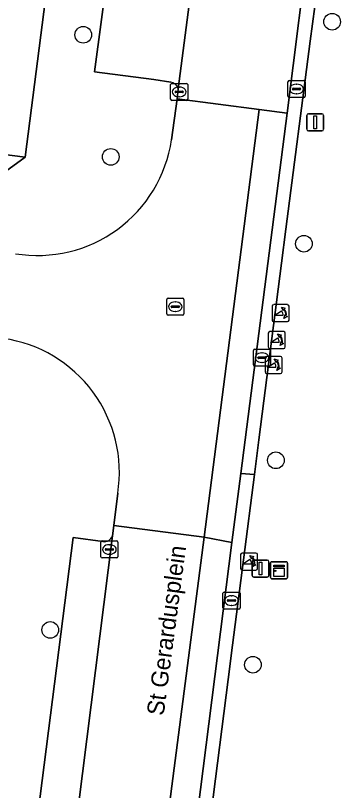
# Model space of a CAD drawing. Extents: x 161692 to 162379, y 380760 to 381678.
# Drawn here: x 162016.68 to 162035.73, y 381271.3 to 381316.74 of the extents above; entities that cross this region are included whole.
import ezdxf

# ---------------------------------------------------------------- set-up
doc = ezdxf.new("R2010")
doc.units = 0
for name, color, linetype in [('IMGEO_Boom', 7, 'Continuous'), ('IMGEO_Erf', 7, 'Continuous'), ('IMGEO_Kast', 7, 'Continuous'), ('IMGEO_Kolk', 7, 'Continuous'), ('IMGEO_Lichtmast', 7, 'Continuous'), ('IMGEO_Openbare_ruimte_label', 7, 'Continuous'), ('IMGEO_Parkeervlak_open', 7, 'Continuous'), ('IMGEO_Poller', 7, 'Continuous'), ('IMGEO_Rijbaan_lokaal_open', 7, 'Continuous'), ('IMGEO_Rioolput', 7, 'Continuous'), ('IMGEO_Voetpad_open', 7, 'Continuous')]:
    doc.layers.add(name, color=color, linetype=linetype)

msp = doc.modelspace()

# ---------------------------------------------------------------- linework, layer by layer
at = {"layer": 'IMGEO_Boom'}
for centre in [(162035.245, 381316.377), (162020.654, 381315.61), (162022.263, 381308.45), (162033.59, 381303.36), (162031.947, 381290.657), (162018.718, 381280.711), (162030.602, 381278.673)]:
    msp.add_circle(centre, 0.489, dxfattribs=at)
at = {"layer": 'IMGEO_Erf'}
msp.add_lwpolyline([(161995.661, 381319.221), (161995.164, 381315.349), (161989.105, 381316.129), (161988.599, 381312.051), (161994.487, 381311.32), (161997.312, 381310.962), (162007.146, 381309.715), (162017.252, 381308.434), (162021.166, 381339.052)], dxfattribs=at)
at = {"layer": 'IMGEO_Kast'}
for p, q in [((162031.634, 381283.786), (162031.634, 381284.627)), ((162031.634, 381284.627), (162031.634, 381283.786)), ((162031.709, 381284.711), (162032.55, 381284.711)), ((162032.55, 381284.711), (162031.709, 381284.711)), ((162032.634, 381284.636), (162032.634, 381283.795)), ((162032.634, 381283.795), (162032.634, 381284.636)), ((162032.559, 381283.711), (162031.718, 381283.711)), ((162031.718, 381283.711), (162032.559, 381283.711))]:
    msp.add_line(p, q, dxfattribs=at)
for points in [[(162031.829, 381284.501), (162032.429, 381284.501), (162032.429, 381284.416), (162031.829, 381284.416), (162031.829, 381284.501)], [(162031.829, 381284.326), (162032.429, 381284.326), (162032.429, 381283.837), (162031.829, 381283.837), (162031.829, 381284.326)]]:
    msp.add_lwpolyline(points, dxfattribs=at)
msp.add_circle((162031.913, 381284.175), 0.0377, dxfattribs=at)
for centre, start, end in [((162031.712, 381284.633), 92.4484, 184.2845), ((162031.712, 381284.633), 92.4484, 184.2845), ((162032.556, 381284.633), 2.4484, 94.2845), ((162032.556, 381284.633), 2.4484, 94.2845), ((162031.712, 381283.789), 182.4484, 274.2845), ((162031.712, 381283.789), 182.4484, 274.2845), ((162032.556, 381283.789), 272.4484, 4.2845), ((162032.556, 381283.789), 272.4484, 4.2845)]:
    msp.add_arc(centre, 0.0779, start, end, dxfattribs=at)
at = {"layer": 'IMGEO_Kolk'}
for p, q in [((162025.775, 381311.834), (162025.775, 381312.686)), ((162025.85, 381312.76), (162026.702, 381312.76)), ((162026.776, 381312.686), (162026.776, 381311.834)), ((162032.656, 381312.005), (162032.656, 381312.857)), ((162032.731, 381312.931), (162033.583, 381312.931)), ((162033.144, 381312.711), (162033.169, 381312.711)), ((162033.657, 381312.857), (162033.657, 381312.005)), ((162026.034, 381312.254), (162026.034, 381312.266)), ((162026.472, 381312.217), (162026.074, 381312.217)), ((162026.077, 381312.303), (162026.475, 381312.303)), ((162026.263, 381312.54), (162026.288, 381312.54)), ((162026.518, 381312.266), (162026.518, 381312.254)), ((162032.915, 381312.425), (162032.915, 381312.437)), ((162033.353, 381312.388), (162032.955, 381312.388)), ((162032.958, 381312.474), (162033.356, 381312.474)), ((162033.399, 381312.437), (162033.399, 381312.425)), ((162026.702, 381311.76), (162025.85, 381311.76)), ((162026.286, 381311.98), (162026.261, 381311.98)), ((162033.583, 381311.931), (162032.731, 381311.931)), ((162033.167, 381312.151), (162033.142, 381312.151)), ((162030.632, 381296.25), (162030.632, 381297.102)), ((162030.707, 381297.176), (162031.559, 381297.176)), ((162031.12, 381296.956), (162031.145, 381296.956)), ((162031.633, 381297.102), (162031.633, 381296.25)), ((162030.891, 381296.67), (162030.891, 381296.682)), ((162031.329, 381296.633), (162030.931, 381296.633)), ((162030.934, 381296.719), (162031.332, 381296.719)), ((162031.143, 381296.396), (162031.118, 381296.396)), ((162031.375, 381296.682), (162031.375, 381296.67)), ((162031.559, 381296.176), (162030.707, 381296.176)), ((162021.687, 381285.004), (162021.687, 381285.856)), ((162021.762, 381285.93), (162022.614, 381285.93)), ((162022.688, 381285.856), (162022.688, 381285.004)), ((162021.946, 381285.424), (162021.946, 381285.436)), ((162021.989, 381285.473), (162022.387, 381285.473)), ((162022.175, 381285.71), (162022.2, 381285.71)), ((162022.43, 381285.436), (162022.43, 381285.424)), ((162022.384, 381285.387), (162021.986, 381285.387)), ((162022.198, 381285.15), (162022.173, 381285.15)), ((162022.614, 381284.93), (162021.762, 381284.93)), ((162028.845, 381282.007), (162028.845, 381282.859)), ((162028.92, 381282.933), (162029.772, 381282.933)), ((162029.333, 381282.713), (162029.358, 381282.713)), ((162029.846, 381282.859), (162029.846, 381282.007)), ((162029.104, 381282.427), (162029.104, 381282.439)), ((162029.542, 381282.39), (162029.144, 381282.39)), ((162029.147, 381282.476), (162029.545, 381282.476)), ((162029.588, 381282.439), (162029.588, 381282.427)), ((162029.772, 381281.933), (162028.92, 381281.933)), ((162029.356, 381282.153), (162029.331, 381282.153))]:
    msp.add_line(p, q, dxfattribs=at)
for points in [[(162025.775, 381311.834), (162025.775, 381312.686)], [(162025.85, 381312.76), (162026.702, 381312.76)], [(162026.776, 381312.686), (162026.776, 381311.834)], [(162032.656, 381312.005), (162032.656, 381312.857)], [(162032.731, 381312.931), (162033.583, 381312.931)], [(162033.657, 381312.857), (162033.657, 381312.005)], [(162026.702, 381311.76), (162025.85, 381311.76)], [(162033.583, 381311.931), (162032.731, 381311.931)], [(162030.632, 381296.25), (162030.632, 381297.102)], [(162030.707, 381297.176), (162031.559, 381297.176)], [(162031.633, 381297.102), (162031.633, 381296.25)], [(162031.559, 381296.176), (162030.707, 381296.176)], [(162021.687, 381285.004), (162021.687, 381285.856)], [(162021.762, 381285.93), (162022.614, 381285.93)], [(162022.688, 381285.856), (162022.688, 381285.004)], [(162022.614, 381284.93), (162021.762, 381284.93)], [(162028.845, 381282.007), (162028.845, 381282.859)], [(162028.92, 381282.933), (162029.772, 381282.933)], [(162029.846, 381282.859), (162029.846, 381282.007)], [(162029.772, 381281.933), (162028.92, 381281.933)]]:
    msp.add_lwpolyline(points, dxfattribs=at)
for centre, radius, start, end in [((162025.852, 381312.684), 0.0765, 91.552, 178.448), ((162025.852, 381312.684), 0.0765, 91.552, 178.448), ((162026.7, 381312.684), 0.0765, 1.552, 88.448), ((162026.7, 381312.684), 0.0765, 1.552, 88.448), ((162032.733, 381312.855), 0.0765, 91.552, 178.448), ((162032.733, 381312.855), 0.0765, 91.552, 178.448), ((162033.581, 381312.855), 0.0765, 1.552, 88.448), ((162033.581, 381312.855), 0.0765, 1.552, 88.448), ((162026.074, 381312.263), 0.0403, 85.8775, 175.7526), ((162026.071, 381312.253), 0.0366, 178.938, 274.7102), ((162026.475, 381312.26), 0.043, 264.8664, 352.4533), ((162026.479, 381312.265), 0.0386, 1.7309, 96.639), ((162032.955, 381312.434), 0.0403, 85.8775, 175.7526), ((162032.952, 381312.424), 0.0366, 178.938, 274.7102), ((162033.356, 381312.431), 0.043, 264.8664, 352.4533), ((162033.36, 381312.436), 0.0386, 1.7309, 96.639), ((162025.852, 381311.836), 0.0765, 181.552, 268.448), ((162025.852, 381311.836), 0.0765, 181.552, 268.448), ((162026.7, 381311.836), 0.0765, 271.552, 358.448), ((162026.7, 381311.836), 0.0765, 271.552, 358.448), ((162032.733, 381312.007), 0.0765, 181.552, 268.448), ((162032.733, 381312.007), 0.0765, 181.552, 268.448), ((162033.581, 381312.007), 0.0765, 271.552, 358.448), ((162033.581, 381312.007), 0.0765, 271.552, 358.448), ((162030.709, 381297.1), 0.0765, 91.552, 178.448), ((162030.709, 381297.1), 0.0765, 91.552, 178.448), ((162031.557, 381297.1), 0.0765, 1.552, 88.448), ((162031.557, 381297.1), 0.0765, 1.552, 88.448), ((162030.931, 381296.679), 0.0403, 85.8775, 175.7526), ((162030.928, 381296.669), 0.0366, 178.938, 274.7102), ((162031.332, 381296.676), 0.043, 264.8664, 352.4533), ((162031.336, 381296.681), 0.0386, 1.7309, 96.639), ((162030.709, 381296.252), 0.0765, 181.552, 268.448), ((162030.709, 381296.252), 0.0765, 181.552, 268.448), ((162031.557, 381296.252), 0.0765, 271.552, 358.448), ((162031.557, 381296.252), 0.0765, 271.552, 358.448), ((162021.764, 381285.854), 0.0765, 91.552, 178.448), ((162021.764, 381285.854), 0.0765, 91.552, 178.448), ((162022.612, 381285.854), 0.0765, 1.552, 88.448), ((162022.612, 381285.854), 0.0765, 1.552, 88.448), ((162021.986, 381285.433), 0.0403, 85.8775, 175.7526), ((162021.983, 381285.423), 0.0366, 178.938, 274.7102), ((162022.387, 381285.43), 0.043, 264.8664, 352.4533), ((162022.391, 381285.435), 0.0386, 1.7309, 96.639), ((162021.764, 381285.006), 0.0765, 181.552, 268.448), ((162021.764, 381285.006), 0.0765, 181.552, 268.448), ((162022.612, 381285.006), 0.0765, 271.552, 358.448), ((162022.612, 381285.006), 0.0765, 271.552, 358.448), ((162028.922, 381282.857), 0.0765, 91.552, 178.448), ((162028.922, 381282.857), 0.0765, 91.552, 178.448), ((162029.77, 381282.857), 0.0765, 1.552, 88.448), ((162029.77, 381282.857), 0.0765, 1.552, 88.448), ((162029.144, 381282.436), 0.0403, 85.8775, 175.7526), ((162029.141, 381282.426), 0.0366, 178.938, 274.7102), ((162029.545, 381282.433), 0.043, 264.8664, 352.4533), ((162029.549, 381282.438), 0.0386, 1.7309, 96.639), ((162028.922, 381282.009), 0.0765, 181.552, 268.448), ((162028.922, 381282.009), 0.0765, 181.552, 268.448), ((162029.77, 381282.009), 0.0765, 271.552, 358.448), ((162029.77, 381282.009), 0.0765, 271.552, 358.448)]:
    msp.add_arc(centre, radius, start, end, dxfattribs=at)
for centre, major_axis, ratio, start_param, end_param in [((162033.143, 381312.431), (-0.387, 0.002), 0.722429, 4.712389, 7.853982), ((162033.168, 381312.431), (-0.39, 0.002), 0.717154, 1.570796, 4.712389), ((162026.262, 381312.26), (-0.387, 0.002), 0.722429, 4.712389, 7.853982), ((162026.287, 381312.26), (-0.39, 0.002), 0.717154, 1.570796, 4.712389), ((162031.119, 381296.676), (-0.387, 0.002), 0.722429, 4.712389, 7.853982), ((162031.144, 381296.676), (-0.39, 0.002), 0.717154, 1.570796, 4.712389), ((162022.174, 381285.43), (-0.387, 0.002), 0.722429, 4.712389, 7.853982), ((162022.199, 381285.43), (-0.39, 0.002), 0.717154, 1.570796, 4.712389), ((162029.332, 381282.433), (-0.387, 0.002), 0.722429, 4.712389, 7.853982), ((162029.357, 381282.433), (-0.39, 0.002), 0.717154, 1.570796, 4.712389)]:
    msp.add_ellipse(centre, major_axis=major_axis, ratio=ratio, start_param=start_param, end_param=end_param, dxfattribs=at)
at = {"layer": 'IMGEO_Lichtmast'}
for p, q in [((162033.752, 381310.078), (162033.752, 381310.878)), ((162033.752, 381310.878), (162033.752, 381310.078)), ((162033.852, 381310.978), (162034.642, 381310.978)), ((162034.642, 381310.978), (162033.852, 381310.978)), ((162034.742, 381310.878), (162034.742, 381310.078)), ((162034.742, 381310.078), (162034.742, 381310.878)), ((162034.642, 381309.978), (162033.852, 381309.978)), ((162033.852, 381309.978), (162034.642, 381309.978)), ((162030.552, 381283.911), (162030.552, 381284.711)), ((162030.552, 381284.711), (162030.552, 381283.911)), ((162030.652, 381284.811), (162031.442, 381284.811)), ((162031.442, 381284.811), (162030.652, 381284.811)), ((162031.542, 381284.711), (162031.542, 381283.911)), ((162031.542, 381283.911), (162031.542, 381284.711)), ((162031.442, 381283.811), (162030.652, 381283.811)), ((162030.652, 381283.811), (162031.442, 381283.811))]:
    msp.add_line(p, q, dxfattribs=at)
for points in [[(162034.172, 381310.853), (162034.322, 381310.853), (162034.322, 381310.103), (162034.172, 381310.103), (162034.172, 381310.853)], [(162030.972, 381284.686), (162031.122, 381284.686), (162031.122, 381283.936), (162030.972, 381283.936), (162030.972, 381284.686)]]:
    msp.add_lwpolyline(points, dxfattribs=at)
for centre, start, end in [((162033.852, 381310.878), 90, 180), ((162033.852, 381310.878), 90, 180), ((162034.642, 381310.878), 0, 90), ((162034.642, 381310.878), 360, 90), ((162033.852, 381310.078), 180, 270), ((162033.852, 381310.078), 180, 270), ((162034.642, 381310.078), 270, 0), ((162034.642, 381310.078), 270, 0), ((162030.652, 381284.711), 90, 180), ((162030.652, 381284.711), 90, 180), ((162031.442, 381284.711), 0, 90), ((162031.442, 381284.711), 360, 90), ((162030.652, 381283.911), 180, 270), ((162030.652, 381283.911), 180, 270), ((162031.442, 381283.911), 270, 0), ((162031.442, 381283.911), 270, 0)]:
    msp.add_arc(centre, 0.1, start, end, dxfattribs=at)
at = {"layer": 'IMGEO_Parkeervlak_open'}
for points in [[(162028.406, 381332.608), (162026.443, 381332.823), (162024.266, 381333.061), (162023.951, 381333.096), (162022.62, 381323.253), (162021.322, 381313.439), (162024.793, 381312.979), (162025.78, 381312.831)], [(162026.227, 381312.442), (162027.445, 381321.903), (162028.924, 381332.977)], [(162035.502, 381327.199), (162035.478, 381327.014), (162035.224, 381325.046), (162034.22, 381317.265), (162033.958, 381315.236), (162032.535, 381304.211), (162032.276, 381302.209), (162030.94, 381291.863), (162030.685, 381289.819), (162029.406, 381279.816), (162029.149, 381277.807), (162028.148, 381269.978), (162027.886, 381267.928), (162027.77, 381267.028)], [(162021.803, 381285.896), (162020.053, 381286.125), (162017.647, 381267.141), (162019.426, 381266.906)], [(162019.864, 381266.409), (162022.365, 381286.225)]]:
    msp.add_lwpolyline(points, dxfattribs=at)
for centre, radius, start, end in [((162025.73, 381312.322), 0.511, 13.5264, 84.411), ((162021.895, 381286.384), 0.497, 259.3692, 341.321)]:
    msp.add_arc(centre, radius, start, end, dxfattribs=at)
at = {"layer": 'IMGEO_Poller'}
for p, q in [((162031.726, 381299.69), (162031.726, 381298.883)), ((162031.726, 381299.69), (162031.726, 381298.883)), ((162032.628, 381299.785), (162031.82, 381299.785)), ((162032.628, 381299.785), (162031.82, 381299.785)), ((162032.722, 381298.883), (162032.722, 381299.69)), ((162032.722, 381298.883), (162032.722, 381299.69)), ((162031.82, 381298.788), (162032.628, 381298.788)), ((162031.82, 381298.788), (162032.628, 381298.788)), ((162032.404, 381298.206), (162031.596, 381298.206)), ((162032.404, 381298.206), (162031.596, 381298.206)), ((162031.502, 381298.111), (162031.502, 381297.304)), ((162031.502, 381298.111), (162031.502, 381297.304)), ((162032.498, 381297.304), (162032.498, 381298.111)), ((162032.498, 381297.304), (162032.498, 381298.111)), ((162031.596, 381297.209), (162032.404, 381297.209)), ((162031.596, 381297.209), (162032.404, 381297.209)), ((162031.311, 381296.649), (162031.311, 381295.842)), ((162031.311, 381296.649), (162031.311, 381295.842)), ((162032.213, 381296.744), (162031.405, 381296.744)), ((162032.213, 381296.744), (162031.405, 381296.744)), ((162032.307, 381295.842), (162032.307, 381296.649)), ((162032.307, 381295.842), (162032.307, 381296.649)), ((162031.405, 381295.747), (162032.213, 381295.747)), ((162031.405, 381295.747), (162032.213, 381295.747)), ((162029.875, 381285.126), (162029.875, 381284.319)), ((162029.875, 381285.126), (162029.875, 381284.319)), ((162030.777, 381285.221), (162029.969, 381285.221)), ((162030.777, 381285.221), (162029.969, 381285.221)), ((162030.871, 381284.319), (162030.871, 381285.126)), ((162030.871, 381284.319), (162030.871, 381285.126)), ((162029.969, 381284.224), (162030.777, 381284.224)), ((162029.969, 381284.224), (162030.777, 381284.224))]:
    msp.add_line(p, q, dxfattribs=at)
for points in [[(162032.405, 381299.514), (162032.393, 381299.441), (162032.268, 381299.646)], [(162032.268, 381299.646), (162032.499, 381299.58), (162032.428, 381299.548)], [(162032.361, 381299.141), (162031.848, 381299.141), (162032.278, 381299.416)], [(162032.421, 381298.969), (162032.487, 381299.2), (162032.517, 381299.132)], [(162032.553, 381299.105), (162032.625, 381299.094), (162032.421, 381298.969)], [(162032.137, 381297.562), (162031.624, 381297.562), (162032.054, 381297.837)], [(162032.181, 381297.935), (162032.169, 381297.862), (162032.044, 381298.067)], [(162032.044, 381298.067), (162032.275, 381298.001), (162032.204, 381297.969)], [(162032.197, 381297.39), (162032.263, 381297.621), (162032.293, 381297.553)], [(162032.329, 381297.526), (162032.401, 381297.515), (162032.197, 381297.39)], [(162031.946, 381296.1), (162031.433, 381296.1), (162031.863, 381296.375)], [(162031.99, 381296.473), (162031.978, 381296.4), (162031.853, 381296.605)], [(162031.853, 381296.605), (162032.084, 381296.539), (162032.013, 381296.507)], [(162032.006, 381295.928), (162032.072, 381296.159), (162032.102, 381296.091)], [(162032.138, 381296.064), (162032.21, 381296.053), (162032.006, 381295.928)], [(162030.554, 381284.95), (162030.542, 381284.877), (162030.417, 381285.082)], [(162030.417, 381285.082), (162030.648, 381285.016), (162030.577, 381284.984)], [(162030.51, 381284.577), (162029.997, 381284.577), (162030.427, 381284.852)], [(162030.57, 381284.405), (162030.636, 381284.636), (162030.666, 381284.568)], [(162030.702, 381284.541), (162030.774, 381284.53), (162030.57, 381284.405)]]:
    msp.add_lwpolyline(points, dxfattribs=at)
for centre, radius, start, end in [((162031.82, 381299.69), 0.0946, 90, 180), ((162031.82, 381299.69), 0.0946, 90, 180), ((162032.047, 381299.201), 0.476, 351.7527, 41.1691), ((162032.047, 381299.201), 0.516, 349.3569, 42.2912), ((162032.628, 381299.69), 0.0946, 0, 90), ((162032.628, 381299.69), 0.0946, 0, 90), ((162032.033, 381299.191), 0.332, 351.3247, 42.4854), ((162031.82, 381298.883), 0.0946, 180, 270), ((162031.82, 381298.883), 0.0946, 180, 270), ((162032.628, 381298.883), 0.0946, 270, 0), ((162032.628, 381298.883), 0.0946, 270, 0), ((162031.596, 381298.111), 0.0946, 90, 180), ((162031.596, 381298.111), 0.0946, 90, 180), ((162032.404, 381298.111), 0.0946, 0, 90), ((162032.404, 381298.111), 0.0946, 0, 90), ((162031.809, 381297.612), 0.332, 351.3247, 42.4854), ((162031.823, 381297.622), 0.476, 351.7527, 41.1691), ((162031.823, 381297.622), 0.516, 349.3569, 42.2912), ((162031.596, 381297.304), 0.0946, 180, 270), ((162031.596, 381297.304), 0.0946, 180, 270), ((162032.404, 381297.304), 0.0946, 270, 0), ((162032.404, 381297.304), 0.0946, 270, 0), ((162031.405, 381296.649), 0.0946, 90, 180), ((162031.405, 381296.649), 0.0946, 90, 180), ((162031.618, 381296.15), 0.332, 351.3247, 42.4854), ((162031.632, 381296.16), 0.476, 351.7527, 41.1691), ((162031.632, 381296.16), 0.516, 349.3569, 42.2912), ((162032.213, 381296.649), 0.0946, 0, 90), ((162032.213, 381296.649), 0.0946, 0, 90), ((162031.405, 381295.842), 0.0946, 180, 270), ((162031.405, 381295.842), 0.0946, 180, 270), ((162032.213, 381295.842), 0.0946, 270, 0), ((162032.213, 381295.842), 0.0946, 270, 0), ((162029.969, 381285.126), 0.0946, 90, 180), ((162029.969, 381285.126), 0.0946, 90, 180), ((162030.196, 381284.637), 0.476, 351.7527, 41.1691), ((162030.196, 381284.637), 0.516, 349.3569, 42.2912), ((162030.777, 381285.126), 0.0946, 0, 90), ((162030.777, 381285.126), 0.0946, 0, 90), ((162030.182, 381284.627), 0.332, 351.3247, 42.4854), ((162029.969, 381284.319), 0.0946, 180, 270), ((162029.969, 381284.319), 0.0946, 180, 270), ((162030.777, 381284.319), 0.0946, 270, 0), ((162030.777, 381284.319), 0.0946, 270, 0)]:
    msp.add_arc(centre, radius, start, end, dxfattribs=at)
at = {"layer": 'IMGEO_Rijbaan_lokaal_open'}
for points in [[(162029.109, 381334.647), (162028.998, 381333.462), (162028.924, 381332.977), (162027.445, 381321.903), (162026.227, 381312.442), (162026.15, 381311.861), (162030.973, 381311.228), (162032.611, 381311.013), (162033.999, 381322.061), (162034.704, 381327.047)], [(162034.704, 381327.047), (162033.999, 381322.061), (162032.611, 381311.013), (162029.889, 381289.886), (162030.685, 381289.819), (162030.94, 381291.863), (162032.276, 381302.209), (162032.535, 381304.211), (162033.958, 381315.236), (162034.22, 381317.265), (162035.224, 381325.046), (162035.478, 381327.014), (162035.502, 381327.199)], [(162030.973, 381311.228), (162026.15, 381311.861), (162025.83, 381309.455)], [(162022.672, 381288.725), (162022.453, 381286.844), (162027.732, 381286.146), (162030.973, 381311.228)], [(162030.685, 381289.819), (162029.889, 381289.886), (162029.368, 381285.839), (162027.018, 381267.348)], [(162027.77, 381267.028), (162027.886, 381267.928), (162028.148, 381269.978), (162029.149, 381277.807), (162029.406, 381279.816), (162030.685, 381289.819)], [(162025.321, 381267.492), (162027.732, 381286.146), (162022.453, 381286.844), (162022.365, 381286.225), (162019.864, 381266.409), (162019.72, 381265.331)], [(162029.368, 381285.839), (162027.732, 381286.146), (162025.321, 381267.492)], [(162027.018, 381267.348), (162029.368, 381285.839)]]:
    msp.add_lwpolyline(points, dxfattribs=at)
msp.add_lwpolyline([(162032.611, 381311.013), (162030.973, 381311.228), (162027.732, 381286.146), (162029.368, 381285.839), (162029.889, 381289.886)], close=True, dxfattribs=at)
for centre, radius, start, end in [((162017.967, 381310.618), 7.948, 260.6857, 351.5832), ((162014.847, 381289.96), 7.922, 351.0315, 81.8327)]:
    msp.add_arc(centre, radius, start, end, dxfattribs=at)
at = {"layer": 'IMGEO_Rioolput'}
for p, q in [((162025.549, 381299.24), (162025.549, 381300.092)), ((162025.624, 381300.166), (162026.476, 381300.166)), ((162026.037, 381299.946), (162026.062, 381299.946)), ((162026.55, 381300.092), (162026.55, 381299.24)), ((162025.808, 381299.66), (162025.808, 381299.672)), ((162026.246, 381299.623), (162025.848, 381299.623)), ((162025.851, 381299.709), (162026.249, 381299.709)), ((162026.292, 381299.672), (162026.292, 381299.66)), ((162026.476, 381299.166), (162025.624, 381299.166)), ((162026.06, 381299.386), (162026.035, 381299.386))]:
    msp.add_line(p, q, dxfattribs=at)
for points in [[(162025.549, 381299.24), (162025.549, 381300.092)], [(162025.624, 381300.166), (162026.476, 381300.166)], [(162026.55, 381300.092), (162026.55, 381299.24)], [(162026.476, 381299.166), (162025.624, 381299.166)]]:
    msp.add_lwpolyline(points, dxfattribs=at)
for centre, radius, start, end in [((162025.626, 381300.09), 0.0765, 91.552, 178.448), ((162025.626, 381300.09), 0.0765, 91.552, 178.448), ((162026.474, 381300.09), 0.0765, 1.552, 88.448), ((162026.474, 381300.09), 0.0765, 1.552, 88.448), ((162025.848, 381299.669), 0.0403, 85.8775, 175.7526), ((162025.845, 381299.659), 0.0366, 178.938, 274.7102), ((162026.249, 381299.666), 0.043, 264.8664, 352.4533), ((162026.253, 381299.671), 0.0386, 1.7309, 96.639), ((162025.626, 381299.242), 0.0765, 181.552, 268.448), ((162025.626, 381299.242), 0.0765, 181.552, 268.448), ((162026.474, 381299.242), 0.0765, 271.552, 358.448), ((162026.474, 381299.242), 0.0765, 271.552, 358.448)]:
    msp.add_arc(centre, radius, start, end, dxfattribs=at)
for centre, major_axis, ratio, start_param, end_param in [((162026.036, 381299.666), (-0.387, 0.002), 0.722429, 4.712389, 7.853982), ((162026.061, 381299.666), (-0.39, 0.002), 0.717154, 1.570796, 4.712389)]:
    msp.add_ellipse(centre, major_axis=major_axis, ratio=ratio, start_param=start_param, end_param=end_param, dxfattribs=at)
at = {"layer": 'IMGEO_Voetpad_open'}
for points in [[(162027.4, 381338.995), (162027.213, 381339.131), (162021.869, 381343.297), (162021.166, 381339.052), (162017.252, 381308.434), (162012.53, 381305.017), (162013.403, 381303.792)], [(162025.78, 381312.831), (162024.793, 381312.979), (162021.322, 381313.439), (162022.62, 381323.253), (162023.951, 381333.096), (162024.266, 381333.061), (162026.443, 381332.823), (162028.406, 381332.608)], [(162012.53, 381305.017), (162017.252, 381308.434), (162007.146, 381309.715), (161997.312, 381310.962), (161994.487, 381311.32), (161988.599, 381312.051), (161987.264, 381312.217), (161957.474, 381315.915), (161941.301, 381318.149)], [(162025.83, 381309.455), (162026.15, 381311.861), (162026.227, 381312.442)], [(162022.453, 381286.844), (162022.672, 381288.725)], [(162022.365, 381286.225), (162022.453, 381286.844)], [(162019.426, 381266.906), (162017.647, 381267.141), (162020.053, 381286.125), (162021.803, 381285.896)]]:
    msp.add_lwpolyline(points, dxfattribs=at)
for centre, radius, start, end in [((162025.73, 381312.322), 0.511, 13.5264, 84.411), ((162017.967, 381310.618), 7.948, 260.6857, 351.5832), ((162014.847, 381289.96), 7.922, 351.0315, 81.8327), ((162021.895, 381286.384), 0.497, 259.3692, 341.321)]:
    msp.add_arc(centre, radius, start, end, dxfattribs=at)

# ---------------------------------------------------------------- texts
at = {"layer": 'IMGEO_Openbare_ruimte_label'}
msp.add_text('St Gerardusplein', height=1, rotation=82.4129, dxfattribs=at).set_placement((162025.362, 381275.648))

doc.saveas('drawing.dxf')
